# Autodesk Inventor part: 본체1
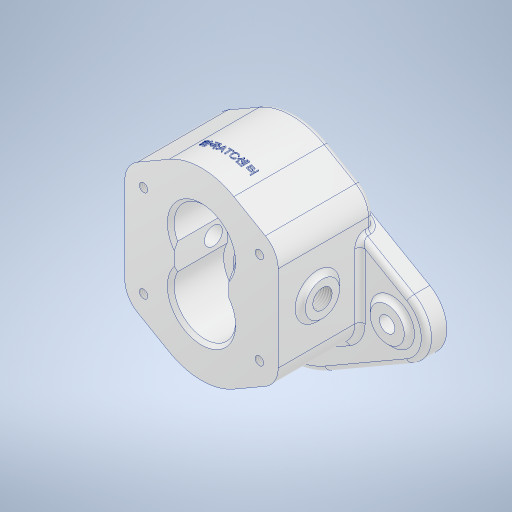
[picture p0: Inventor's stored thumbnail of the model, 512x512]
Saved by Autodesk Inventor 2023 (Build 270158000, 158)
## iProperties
Created: 2025-11
Part Number: 본체1
Material: 알루미늄 6061
Document SubType Name: Modeling
Designer: home
Mass: 1255.67 g
Surface Area: 576.33 cm^2
Volume: 465.061 cm^3
Density: 2.7 g/cm^3
Appearance: 알루미늄 - 평지
Author: home
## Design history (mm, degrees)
sketch "스케치1"
  geometry: L1 (26, 45.033)-(74, 17.321); L2 (26, -45.033)-(74, -17.321); L3 (0, 52)-(0, -52); L4 (-26, 45.033)-(-74, 17.321); L5 (-26, -45.033)-(-74, -17.321); C1 r 10 at (-64, 0); C2 r 10 at (64, 0); A1 r 52 centre (0, 0) between (26, 45.033) and (-26, 45.033); A2 r 20 centre (64, 0) between (74, -17.321) and (74, 17.321); A3 r 20 centre (-64, 0) between (-74, 17.321) and (-74, -17.321); A4 r 52 centre (0, 0) between (-26, -45.033) and (26, -45.033); 4 further points
  constraints: 14 point on circle, 10 end point, 6 centre point, 6 tangent, 5 symmetric about line, 2 coincident, 2 horizontal alignment, 1 equal radius, 1 midpoint, 1 vertical, 1 other
  dimensions: "d0" = 168 distance of point (-84, 0) point (84, 0); "d1" = 128 distance of C1.centre C2.centre; "d2" = 64 distance from line of C1.centre L3; "d3" = 20 radius of A3; "d5" = 20 diameter of C2; "d33" = 52 radius of A1
extrude "돌출1" new body sketch "스케치1" distance "d6" = 15; taper "d7" = 0 deg
extrude "돌출2" join sketch "스케치1" distance "d8" = 12; taper "d9" = 0 deg
fillet "모깎기1" dims "d10" = 3
sketch "스케치2"
  geometry: C1 r 10 at (0, 0) reference; C2 r 10 at (128, 0) reference; 3 further points
  constraints: 2 coincident
hole "구멍1" sketch "스케치2" at (0, 0), (128, 0) diameter "d11" = 9; stored, may be unused: countersink angle "d15" = 90 deg, drill point angle "d17" = 0 deg; dims "d12" = 12, "d13" = 4, "d14" = 2, "d16" = 16
sketch "스케치3"
  geometry: C1 r 25 at (0, 0)
  constraints: 1 centre point
  dimensions: "d18" = 50 diameter of C1
extrude "돌출3" join sketch "스케치3" distance "d19" = 4; taper "d20" = 0 deg
node "작업 평면1"
sketch "스케치4"
  geometry: L1 (19, 64.909)-(37.5, 54.228); L2 (45, 41.238)-(45, -9.238); L3 (37.5, -22.228)-(19, -32.909); L4 (0, -111.174)-(0, 92.407); L5 (-19, 64.909)-(-37.5, 54.228); L6 (-45, 41.238)-(-45, -9.238); L7 (-37.5, -22.228)-(-19, -32.909); L8 (0, 0)-(45, 0); A1 r 38 centre (0, 32) between (19, 64.909) and (-19, 64.909); A2 r 38 centre (0, 0) between (-19, -32.909) and (19, -32.909); A3 r 15 centre (30, 41.238) between (45, 41.238) and (37.5, 54.228); A4 r 15 centre (-30, 41.238) between (-37.5, 54.228) and (-45, 41.238); A5 r 15 centre (-30, -9.238) between (-45, -9.238) and (-37.5, -22.228); A6 r 15 centre (30, -9.238) between (37.5, -22.228) and (45, -9.238); 4 further points
  constraints: 16 end point, 12 point on circle, 12 tangent, 11 point on line, 6 centre point, 4 equal radius, 2 symmetric about line, 1 parallel, 1 perpendicular, 1 vertical
  dimensions: "d22" = 90 distance between parallel lines of L2 L6; "d24" = 38 radius of A2; "d25" = 15 radius of A3; "d27" = 60 deg angle of L3 L1; "d28" = 30 deg angle of L3 L8; "d39" = 32 distance of L8.start A1.centre
fillet "모깎기2" dims "d30" = 3
extrude "돌출4" join sketch "스케치4" distance "d31" = 56; taper "d32" = 0 deg
sketch "스케치9"
  geometry: L1 (-9.238, 60)-(41.238, 60) reference; C1 r 10 at (16, 37); 1 further point
  constraints: 1 centre point
  dimensions: "d74" = 23 distance from line of L1 C1.centre; "d75" = 16 horizontal distance of point (0, 0) C1.centre; "d76" = 20 diameter of C1
extrude "돌출7" join sketch "스케치9" stored distance "d77" = 96; taper "d78" = 0 deg
sketch "스케치7"
  geometry: L1 (32, 60)-(32, 0); L2 (0, -4)-(0, 60); L3 (94.4, 60)-(-76.4, 60) reference; L4 (17.321, 0)-(45.033, 0) reference; L5 (-25, -4)-(25, -4) reference; L6 (52, 0)-(45.033, 0) reference; L7 (32, 60)-(50, 60); L8 (41.238, 60)-(54.228, 60) reference; L9 (50, 29)-(44.5, 29); L10 (43.5, 28)-(43.5, 14); L11 (43.5, 14)-(32, 14); L12 (50, 29)-(50, 60); L13 (44.5, 29)-(43.5, 28); L14 (-15, -3.3)-(-15, 3); L15 (-14.7, 3.3)-(-10.5, 3.3); L16 (-10.5, 3.3)-(-10.5, 14); L17 (-10.5, 14)-(-11.5, 14); L18 (-11.5, 14)-(-11.5, 28); L19 (-12.5, 29)-(-18, 29); L20 (-18, 29)-(-18, 60); L21 (-32.909, 60)-(-22.228, 60) reference; L22 (0, 60)-(-18, 60); L23 (-11.5, 28)-(-12.5, 29); L24 (0, -4)-(-15.404, -4); L25 (-15, -3.3)-(-15.404, -4); A1 r 0.3 centre (-14.7, 3) between (-14.7, 3.3) and (-15, 3); 4 further points
  constraints: 39 end point, 12 point on line, 7 vertical, 4 perpendicular, 2 midpoint, 2 point on circle, 2 tangent, 1 centre point, 1 collinear, 1 horizontal, 1 parallel
  dimensions: "d46" = 32 distance between parallel lines of L2 L1; "d47" = 31 distance of L9.start L7.end; "d48" = 15 distance of point (43.5, 29) L10.end; "d49" = 36 diameter of L12 L1; "d50" = 23 diameter of L10 L1; "d51" = 1 distance of L9.end point (43.5, 29); "d52" = 45 deg angle of L9 L13; "d53" = 31 distance of L19.end L20.end; "d54" = 15 distance of L17.end point (-11.5, 29); "d56" = 30 diameter of L14 L2; "d57" = 21 diameter of L16 L2; "d58" = 23 diameter of L18 point (0, 28); "d59" = 36 diameter of L20 L2; "d60" = 1 distance of L18.end point (-11.5, 29); "d61" = 45 deg angle of L18 L23; "d62" = 7.3 distance between parallel lines of L15 L5; "d63" = 30 deg angle of L25 L14; "d64" = 0.7 distance from line of L24 L14.start; "d65" = 0.3 radius of A1
revolve "회전1" stored, may be unused: angle "d66" = 90 deg
revolve "회전2" stored, may be unused: angle "d67" = 360 deg
chamfer "모따기1" distance "d68" = 2; stored, may be unused: second distance "d69" = 2, angle "d70" = 45 deg
sketch "스케치8"
  geometry: L1 (16, 0)-(-16, 0); L2 (-16, 0)-(-16, 32); L3 (-16, 32)-(16, 32); L4 (16, 32)-(16, 0); A1 r 38 centre (0, 0) between (-19, -32.909) and (19, -32.909) reference; A2 r 20 centre (0, 32) between (12, 16) and (-12, 16) reference; 1 further point
  constraints: 8 end point, 2 midpoint, 2 parallel, 1 coincident, 1 horizontal, 1 perpendicular
  dimensions: "d71" = 32 distance of L2.end L3.end
extrude "돌출6" cut sketch "스케치8" stored distance "d72" = 10; taper "d73" = 0 deg
fillet "모깎기4" dims "d79" = 3
fillet "모깎기5" dims "d80" = 3
fillet "모깎기6" dims "d81" = 3
sketch "스케치10"
  geometry: C1 r 10 at (0, 0) reference; 2 further points
  constraints: 1 coincident
hole "구멍2" sketch "스케치10" at (0, 0) diameter "d83" = 10.5; stored, may be unused: countersink angle "d89" = 90 deg, drill point angle "d91" = 0 deg; dims "d84" = 11, "d85" = 0.62479, "d86" = 10.589, "d87" = 4, "d88" = 2, "d90" = 8
sketch "스케치11"
  geometry: L1 (-30, 41.238)-(30, -9.238); L2 (30, -9.238)-(-30, -9.238); L3 (-30, -9.238)-(30, 41.238); L4 (-34, -11)-(34, -11); L5 (34, -11)-(34, 43); L6 (34, 43)-(-34, 43); L7 (-34, 43)-(-34, -11); L8 (-34, -11)-(34, 43); L9 (34, -11)-(-34, 43); C1 r 15.404 at (0, 0) reference; A1 r 15 centre (30, 41.238) between (45, 41.238) and (37.5, 54.228) reference; A2 r 15 centre (-30, 41.238) between (-37.5, 54.228) and (-45, 41.238) reference; A3 r 15 centre (-30, -9.238) between (-45, -9.238) and (-37.5, -22.228) reference; A4 r 38 centre (0, 0) between (-19, -32.909) and (19, -32.909) reference; 6 further points
  constraints: 18 end point, 4 coincident, 4 midpoint, 2 horizontal, 2 parallel, 1 perpendicular
  dimensions: "d92" = 68 distance of L5.end L6.end; "d93" = 54 distance of L6.end L4.start; "d94" = 16 distance of A4.centre point (0, 16)
hole "구멍3" sketch "스케치11" at (-34, 43), (-34, -11), (34, -11), (34, 43) diameter "d95" = 4.917; stored, may be unused: countersink angle "d99" = 90 deg, drill point angle "d101" = 118 deg; dims "d96" = 12, "d97" = 4, "d98" = 2, "d100" = 14
node "작업 평면2"
sketch "스케치12"
  geometry: L1 (-19, 0)-(19, 0) reference; 2 further points
  constraints: 1 vertical alignment, 1 other
  dimensions: "d102" = 16 distance from line of L1 point (0, -16)
feature "엠보싱1" sketch "스케치12" dims "d103" = 0.5, "d104" = 0
chamfer "모따기2" distance "d105" = 1; stored, may be unused: second distance "d106" = 2, angle "d107" = 45 deg
node "솔리드1"
mirror "미러1"
feature "A9D066F2-1C7D-4E18-AEED-F7BC21143FA4" dims "d11" = 9, "d12" = 12, "d13" = 4, "d14" = 2, "d15" = 90 deg, "d16" = 16, "d17" = 0
other parameters: "d21" = -64
